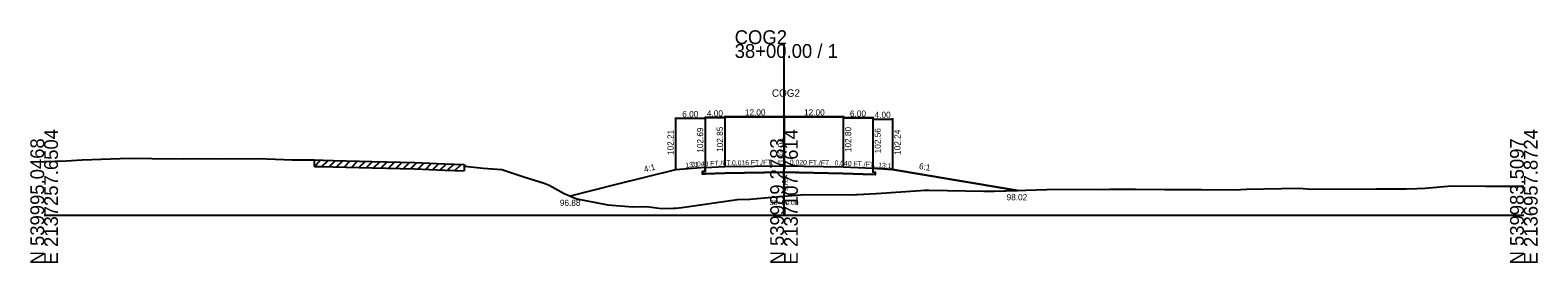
# Model space of a CAD drawing. Extents: x -13397 to 2303, y -10 to 39059.
# Drawn here: x 997.2 to 1302.8, y 15990.3 to 16037.6 of the extents above; entities that cross this region are included whole.
import ezdxf

# ---------------------------------------------------------------- set-up
doc = ezdxf.new("R2010")
doc.units = 0
for name, color, linetype in [('Level 5', 7, 'Continuous'), ('Level 53', 7, 'Continuous'), ('Level 54', 7, 'Continuous'), ('Level 55', 7, 'Continuous'), ('Level 7', 7, 'Continuous'), ('RD_GPK_XS_Cell', 7, 'Continuous'), ('RD_XS_EwShp', 7, 'Continuous'), ('RD_XS_ExGround', 7, 'Continuous'), ('RD_XS_ExPaveRet', 7, 'Continuous'), ('RD_XS_Pave', 7, 'Continuous'), ('RD_XS_TX_Baseline', 7, 'Continuous'), ('RD_XS_TX_Elev_EX', 7, 'Continuous'), ('RD_XS_TX_Elev_PR', 7, 'Continuous'), ('RD_XS_TX_Station', 7, 'Continuous')]:
    doc.layers.add(name, color=color, linetype=linetype)

msp = doc.modelspace()

# ---------------------------------------------------------------- linework, layer by layer
at = {"layer": 'Level 5'}
for p, q in [((1134, 16008.86), (1133.5, 16008.84)), ((1133.5, 16008.84), (1133.5, 16008.34)), ((1134, 16009.69), (1134, 16008.86)), ((1150, 16008.71), (1138, 16008.52)), ((1150, 16008.71), (1138, 16008.52)), ((1150, 16008.71), (1138, 16008.52)), ((1138, 16008.52), (1150, 16008.71)), ((1138, 16008.52), (1150, 16008.71)), ((1162, 16008.47), (1150, 16008.71)), ((1162, 16008.47), (1150, 16008.71)), ((1150, 16008.71), (1162, 16008.47)), ((1150, 16008.71), (1162, 16008.47)), ((1150, 16008.71), (1162, 16008.47)), ((1168, 16009.56), (1168, 16008.73)), ((1168, 16008.73), (1168.5, 16008.71)), ((1168.5, 16008.71), (1168.5, 16008.21)), ((1133.5, 16008.34), (1134, 16008.36)), ((1138, 16008.52), (1134, 16008.36)), ((1138, 16008.52), (1134, 16008.36)), ((1138, 16008.52), (1134, 16008.36)), ((1134, 16008.36), (1138, 16008.52)), ((1168, 16008.23), (1162, 16008.47)), ((1162, 16008.47), (1168, 16008.23)), ((1162, 16008.47), (1168, 16008.23)), ((1162, 16008.47), (1168, 16008.23)), ((1168.5, 16008.21), (1168, 16008.23))]:
    msp.add_line(p, q, dxfattribs=at)
at = {"layer": 'Level 54'}
for p, q in [((1128, 16019.84), (1128, 16009.41)), ((1134, 16019.64), (1128, 16019.64)), ((1134, 16020), (1134, 16009.89)), ((1134, 16020), (1134, 16009.89)), ((1134, 16020), (1134, 16009.89)), ((1134, 16020), (1134, 16009.89)), ((1134, 16019.84), (1134, 16009.89)), ((1134, 16019.8), (1138, 16019.8)), ((1134, 16019.8), (1138, 16019.8)), ((1134, 16019.8), (1138, 16019.8)), ((1138, 16019.8), (1134, 16019.8)), ((1138, 16020.19), (1138, 16010.05)), ((1138, 16020.19), (1138, 16010.05)), ((1138, 16020.19), (1138, 16010.05)), ((1138, 16020.19), (1138, 16010.05)), ((1138, 16020.19), (1138, 16010.05)), ((1138, 16020), (1138, 16010.05)), ((1138, 16020), (1138, 16010.05)), ((1138, 16020), (1138, 16010.05)), ((1138, 16020), (1138, 16010.05)), ((1138, 16019.99), (1150, 16019.99)), ((1138, 16019.99), (1150, 16019.99)), ((1138, 16019.99), (1150, 16019.99)), ((1150, 16019.99), (1138, 16019.99)), ((1150, 16019.99), (1138, 16019.99)), ((1150, 16020.19), (1150, 16010.24)), ((1150, 16020.19), (1150, 16010.24)), ((1150, 16020.19), (1150, 16010.24)), ((1150, 16020.19), (1150, 16010.24)), ((1150, 16020.19), (1150, 16010.24)), ((1150, 16020.19), (1150, 16010.24)), ((1150, 16020.19), (1150, 16010.24)), ((1150, 16020.19), (1150, 16010.24)), ((1150, 16020.19), (1150, 16010.24)), ((1150, 16020.19), (1150, 16010.24)), ((1150, 16019.99), (1162, 16019.99)), ((1150, 16019.99), (1162, 16019.99)), ((1162, 16019.99), (1150, 16019.99)), ((1162, 16019.99), (1150, 16019.99)), ((1162, 16019.99), (1150, 16019.99)), ((1162, 16020.19), (1162, 16010)), ((1162, 16020.19), (1162, 16010)), ((1162, 16020.19), (1162, 16010)), ((1162, 16020.19), (1162, 16010)), ((1162, 16020.19), (1162, 16010)), ((1162, 16019.95), (1162, 16010)), ((1162, 16019.95), (1162, 16010)), ((1162, 16019.95), (1162, 16010)), ((1162, 16019.95), (1162, 16010)), ((1162, 16019.75), (1168, 16019.75)), ((1168, 16019.75), (1162, 16019.75)), ((1168, 16019.75), (1162, 16019.75)), ((1168, 16019.75), (1162, 16019.75)), ((1168, 16019.95), (1168, 16009.76)), ((1168, 16019.95), (1168, 16009.76)), ((1168, 16019.95), (1168, 16009.76)), ((1168, 16019.95), (1168, 16009.76)), ((1168, 16019.71), (1168, 16009.76)), ((1168, 16019.51), (1172, 16019.51)), ((1172, 16019.71), (1172, 16009.44))]:
    msp.add_line(p, q, dxfattribs=at)
at = {"layer": 'Level 7'}
for p, q in [((1128, 16009.21), (1116, 16006.21)), ((1134, 16009.69), (1128, 16009.21)), ((1168, 16009.56), (1172, 16009.24)), ((1172, 16009.24), (1184, 16007.24)), ((1116, 16006.21), (1106.67, 16003.88)), ((1184, 16007.24), (1197.32, 16005.02))]:
    msp.add_line(p, q, dxfattribs=at)
at = {"layer": 'RD_GPK_XS_Cell'}
for p, q in [((1150, 16000), (1150, 16034.74)), ((1000, 16000), (1150, 16000)), ((1150, 16000), (1300, 16000))]:
    msp.add_line(p, q, dxfattribs=at)
at = {"layer": 'RD_XS_EwShp'}
msp.add_lwpolyline([(1192.63, 16004.85), (1197.32, 16005.02), (1184, 16007.24), (1172, 16009.24), (1168, 16009.56), (1168, 16008.73), (1168.5, 16008.71), (1168.5, 16008.21), (1168, 16008.23), (1162, 16008.47), (1150, 16008.71), (1138, 16008.52), (1134, 16008.36), (1133.5, 16008.34), (1133.5, 16008.84), (1134, 16008.86), (1134, 16009.69), (1128, 16009.21), (1116, 16006.21), (1106.67, 16003.88), (1107.99, 16003.33), (1114.3, 16002.08), (1119.32, 16001.66), (1122.09, 16001.77), (1125.14, 16001.37), (1127.59, 16001.39), (1128.09, 16001.4), (1129.29, 16001.54), (1140.54, 16003.15), (1143.04, 16003.26), (1147.55, 16003.63), (1150, 16003.84), (1154.13, 16004.18), (1164.18, 16004.16), (1164.59, 16004.18), (1164.92, 16004.18), (1168.7, 16004.43), (1177.7, 16005.02), (1178.47, 16005.05), (1179.44, 16005.05), (1190.49, 16004.85)], close=True, dxfattribs=at)
at = {"layer": 'RD_XS_ExGround'}
for p, q in [((1000, 16010.87), (1004.44, 16011.04)), ((1004.44, 16011.04), (1007.68, 16011.24)), ((1007.68, 16011.24), (1017.38, 16011.58)), ((1017.38, 16011.58), (1021.83, 16011.54)), ((1021.83, 16011.54), (1028.25, 16011.41)), ((1028.25, 16011.41), (1030.33, 16011.5)), ((1030.33, 16011.5), (1036.1, 16011.47)), ((1036.1, 16011.47), (1043.46, 16011.51)), ((1043.46, 16011.51), (1050.26, 16011.26)), ((1050.26, 16011.26), (1051.42, 16011.26)), ((1051.42, 16011.26), (1054.79, 16011.21)), ((1054.79, 16011.21), (1056.58, 16011.15)), ((1056.58, 16011.15), (1058.62, 16011.11)), ((1058.62, 16011.11), (1066.51, 16010.89)), ((1066.51, 16010.89), (1075.17, 16010.68)), ((1075.17, 16010.68), (1081.24, 16010.44)), ((1081.24, 16010.44), (1085.16, 16010.28)), ((1085.16, 16010.28), (1085.3, 16009.98)), ((1085.3, 16009.98), (1089.03, 16009.56)), ((1089.03, 16009.56), (1092.79, 16009.28)), ((1092.79, 16009.28), (1097.26, 16007.78)), ((1097.26, 16007.78), (1101.37, 16006.48)), ((1101.37, 16006.48), (1102.41, 16006.08)), ((1102.41, 16006.08), (1105.4, 16004.42)), ((1243.77, 16005.31), (1254.4, 16005.51)), ((1254.4, 16005.51), (1256.95, 16005.3)), ((1278.34, 16005.43), (1279.97, 16005.5)), ((1279.97, 16005.5), (1285.33, 16005.96)), ((1285.33, 16005.96), (1292.23, 16005.86)), ((1292.23, 16005.86), (1300, 16005.88)), ((1105.4, 16004.42), (1107.99, 16003.33)), ((1107.99, 16003.33), (1114.3, 16002.08)), ((1129.29, 16001.54), (1140.54, 16003.15)), ((1140.54, 16003.15), (1143.04, 16003.26)), ((1143.04, 16003.26), (1147.55, 16003.63)), ((1147.55, 16003.63), (1150, 16003.84)), ((1150, 16003.84), (1154.13, 16004.18)), ((1154.13, 16004.18), (1164.18, 16004.16)), ((1164.18, 16004.16), (1164.59, 16004.18)), ((1164.59, 16004.18), (1164.92, 16004.18)), ((1164.92, 16004.18), (1168.7, 16004.43)), ((1168.7, 16004.43), (1177.7, 16005.02)), ((1177.7, 16005.02), (1178.47, 16005.05)), ((1178.47, 16005.05), (1179.44, 16005.05)), ((1179.44, 16005.05), (1190.49, 16004.85)), ((1190.49, 16004.85), (1192.63, 16004.85)), ((1192.63, 16004.85), (1203.27, 16005.24)), ((1203.27, 16005.24), (1211.23, 16005.27)), ((1211.23, 16005.27), (1213.89, 16005.23)), ((1213.89, 16005.23), (1216.05, 16005.25)), ((1216.05, 16005.25), (1221.25, 16005.25)), ((1221.25, 16005.25), (1227.18, 16005.24)), ((1227.18, 16005.24), (1228.09, 16005.24)), ((1228.09, 16005.24), (1234.62, 16005.22)), ((1234.62, 16005.22), (1241.62, 16005.17)), ((1241.62, 16005.17), (1242.55, 16005.18)), ((1242.55, 16005.18), (1243.77, 16005.31)), ((1256.95, 16005.3), (1270.08, 16005.34)), ((1270.08, 16005.34), (1276.12, 16005.38)), ((1276.12, 16005.38), (1278.34, 16005.43)), ((1114.3, 16002.08), (1119.32, 16001.66)), ((1119.32, 16001.66), (1122.09, 16001.77)), ((1122.09, 16001.77), (1125.14, 16001.37)), ((1125.14, 16001.37), (1127.59, 16001.39)), ((1127.59, 16001.39), (1128.09, 16001.4)), ((1128.09, 16001.4), (1129.29, 16001.54))]:
    msp.add_line(p, q, dxfattribs=at)
at = {"layer": 'RD_XS_ExPaveRet'}
for p, q in [((1054.79, 16009.91), (1054.79, 16011.21)), ((1054.79, 16009.91), (1056.05, 16011.17)), ((1054.79, 16009.91), (1056.58, 16009.85)), ((1056.29, 16009.86), (1057.56, 16011.13)), ((1056.58, 16009.85), (1058.62, 16009.81)), ((1057.79, 16009.83), (1059.06, 16011.1)), ((1058.62, 16009.81), (1066.51, 16009.59)), ((1059.29, 16009.79), (1060.56, 16011.06)), ((1060.79, 16009.75), (1062.06, 16011.02)), ((1062.29, 16009.71), (1063.56, 16010.98)), ((1063.79, 16009.67), (1065.06, 16010.93)), ((1065.29, 16009.63), (1066.56, 16010.89)), ((1066.51, 16009.59), (1075.17, 16009.38)), ((1066.79, 16009.59), (1068.06, 16010.86)), ((1068.29, 16009.55), (1069.56, 16010.82)), ((1069.79, 16009.51), (1071.06, 16010.78)), ((1071.29, 16009.48), (1072.56, 16010.75)), ((1072.79, 16009.44), (1074.06, 16010.71)), ((1074.29, 16009.4), (1075.56, 16010.67)), ((1075.17, 16009.38), (1081.24, 16009.14)), ((1075.79, 16009.36), (1077.04, 16010.61)), ((1077.29, 16009.3), (1078.54, 16010.55)), ((1078.79, 16009.24), (1080.04, 16010.49)), ((1080.29, 16009.18), (1081.54, 16010.43)), ((1081.24, 16009.14), (1085.16, 16008.98)), ((1081.79, 16009.12), (1083.04, 16010.36)), ((1083.29, 16009.05), (1084.54, 16010.3)), ((1085.16, 16010.28), (1085.16, 16008.98))]:
    msp.add_line(p, q, dxfattribs=at)
at = {"layer": 'RD_XS_Pave'}
for p, q in [((1134, 16009.69), (1138, 16009.85)), ((1138, 16009.85), (1150, 16010.04)), ((1150, 16010.04), (1162, 16009.8)), ((1162, 16009.8), (1168, 16009.56))]:
    msp.add_line(p, q, dxfattribs=at)

# ---------------------------------------------------------------- texts
at = {"layer": 'Level 53'}
for s, rotation, p in [('102.69', 90, (1133.62, 16012.69)), ('102.85', 90, (1137.63, 16012.85)), ('102.85', 90, (1137.63, 16012.85)), ('102.85', 90, (1137.63, 16012.85)), ('102.80', 90, (1163.63, 16012.8)), ('102.80', 90, (1163.63, 16012.8)), ('102.80', 90, (1163.63, 16012.8)), ('102.21', 90, (1127.62, 16012.21)), ('102.56', 90, (1169.62, 16012.56)), ('102.24', 90, (1173.62, 16012.24)), ('4:1', 14.0362, (1121.76, 16008.68)), ('6:1', 350.5377, (1177.3, 16009.37))]:
    msp.add_text(s, height=1.25, rotation=rotation, dxfattribs=at).set_placement(p)
for s, p in [('96.88', (1104.55, 16001.88)), ('98.02', (1195.13, 16003.02))]:
    msp.add_text(s, height=1.25, dxfattribs=at).set_placement(p)
at = {"layer": 'Level 54'}
for s, p in [('6.00', (1129.37, 16019.89)), ('4.00', (1134.37, 16020.05)), ('4.00', (1134.37, 16020.05)), ('4.00', (1134.37, 16020.05)), ('4.00', (1134.37, 16020.05)), ('12.00', (1142.07, 16020.24)), ('12.00', (1142.07, 16020.24)), ('12.00', (1142.07, 16020.24)), ('12.00', (1142.07, 16020.24)), ('12.00', (1142.07, 16020.24)), ('12.00', (1154.07, 16020.24)), ('12.00', (1154.07, 16020.24)), ('12.00', (1154.07, 16020.24)), ('12.00', (1154.07, 16020.24)), ('12.00', (1154.07, 16020.24)), ('6.00', (1163.37, 16020)), ('6.00', (1163.37, 16020)), ('6.00', (1163.37, 16020)), ('6.00', (1163.37, 16020)), ('4.00', (1168.37, 16019.76))]:
    msp.add_text(s, height=1.25, dxfattribs=at).set_placement(p)
at = {"layer": 'Level 55'}
for s, rotation, p in [('13:1', 4.5739, (1130.03, 16009.63)), ('0.040 FT./FT.', 2.2906, (1131.22, 16009.83)), ('0.040 FT./FT.', 2.2906, (1131.22, 16009.83)), ('0.040 FT./FT.', 2.2906, (1131.22, 16009.83)), ('0.040 FT./FT.', 2.2906, (1131.22, 16009.83)), ('0.016 FT./FT.', 0.8952, (1139.46, 16010.13)), ('0.016 FT./FT.', 0.8952, (1139.46, 16010.13)), ('0.016 FT./FT.', 0.8952, (1139.46, 16010.13)), ('0.016 FT./FT.', 0.8952, (1139.46, 16010.13)), ('0.016 FT./FT.', 0.8952, (1139.46, 16010.13)), ('0.020 FT./FT.', 358.8542, (1151.18, 16010.27)), ('0.020 FT./FT.', 358.8542, (1151.18, 16010.27)), ('0.020 FT./FT.', 358.8542, (1151.18, 16010.27)), ('0.020 FT./FT.', 358.8542, (1151.18, 16010.27)), ('0.020 FT./FT.', 358.8542, (1151.18, 16010.27)), ('0.040 FT./FT.', 357.7094, (1160.24, 16010.12)), ('0.040 FT./FT.', 357.7094, (1160.24, 16010.12)), ('0.040 FT./FT.', 357.7094, (1160.24, 16010.12)), ('0.040 FT./FT.', 357.7094, (1160.24, 16010.12)), ('13:1', 355.4261, (1169.07, 16009.73))]:
    msp.add_text(s, height=1, rotation=rotation, dxfattribs=at).set_placement(p)
at = {"layer": 'RD_GPK_XS_Cell'}
for s, p in [('COG2', (1140, 16034.74)), ('38+00.00 / 1', (1140, 16031.94))]:
    msp.add_text(s, height=2.8, dxfattribs=at).set_placement(p)
for s, p in [('N 539995.0468', (1000, 15990)), ('E 2137257.6504', (1002.8, 15990)), ('N 539989.2783', (1150, 15990)), ('E 2137107.7614', (1152.8, 15990)), ('N 539983.5097', (1300, 15990)), ('E 2136957.8724', (1302.8, 15990))]:
    msp.add_text(s, height=2.8, rotation=90, dxfattribs=at).set_placement(p)
at = {"layer": 'RD_XS_TX_Baseline'}
msp.add_text('COG2', height=1.5, dxfattribs=at).set_placement((1147.55, 16024.04))
at = {"layer": 'RD_XS_TX_Elev_EX'}
msp.add_text('96.84', height=1, rotation=90, dxfattribs=at).set_placement((1150.75, 16004.84))
at = {"layer": 'RD_XS_TX_Elev_PR'}
msp.add_text(' 103.04', height=1.25, rotation=90, dxfattribs=at).set_placement((1150, 16010.04))
at = {"layer": 'RD_XS_TX_Station'}
msp.add_text('38+00.00', height=1, dxfattribs=at).set_placement((1147.15, 16002.04))

doc.saveas('drawing.dxf')
